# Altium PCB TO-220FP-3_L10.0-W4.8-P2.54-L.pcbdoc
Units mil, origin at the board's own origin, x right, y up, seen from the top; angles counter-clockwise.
Board outline 920 x 720.75 mil, 2 copper layers (Top Layer, Bottom Layer), stack 0 mil thick; 1 components, 0 nets, 3 pads, 0 vias.
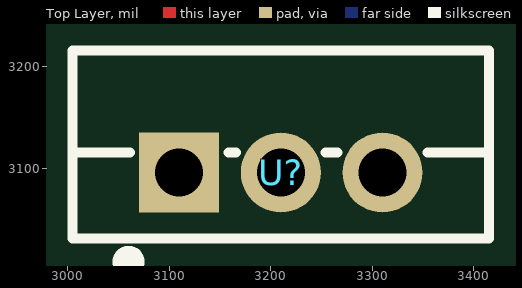
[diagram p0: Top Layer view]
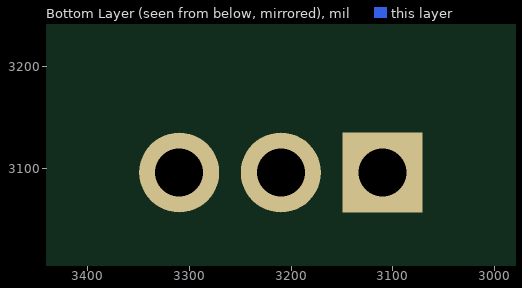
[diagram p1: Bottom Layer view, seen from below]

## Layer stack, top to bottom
Top Layer: signal copper (thickness not stored)
Bottom Layer: signal copper (thickness not stored)

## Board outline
3670,2750 2750,2750 2750,3470.75 3670,3470.75

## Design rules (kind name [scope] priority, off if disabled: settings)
PasteMaskExpansion "Paste Mask Expansion" [All] p1: expansion=0
SolderMaskExpansion "Solder Mask Expansion" [IsVia] p1: expansion=-1000 istentingtop=TRUE
SolderMaskExpansion "Solder Mask Expansion" [All] p2: expansion=2 istentingtop=FALSE

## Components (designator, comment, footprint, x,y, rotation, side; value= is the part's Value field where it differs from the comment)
U? "" TO-220FP-3_L10.0-W4.8-P2.54-L 3210,3095.75 r0 top

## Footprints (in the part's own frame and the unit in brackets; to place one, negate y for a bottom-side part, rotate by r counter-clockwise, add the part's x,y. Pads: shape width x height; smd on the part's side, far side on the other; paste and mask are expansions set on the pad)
TO-220FP-3_L10.0-W4.8-P2.54-L [mm]
  rect 2x2 hole 1.2: 1(-2.54,0)
  round 2 hole 1.2: 2(0,0) 3(2.54,0)
  silkscreen extent -5.21,-2.43 5.21,3.05

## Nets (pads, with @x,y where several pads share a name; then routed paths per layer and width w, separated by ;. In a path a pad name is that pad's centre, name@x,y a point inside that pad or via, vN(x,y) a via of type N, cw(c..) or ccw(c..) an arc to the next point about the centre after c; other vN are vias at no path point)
pads on no net: U?.1 U?.2 U?.3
